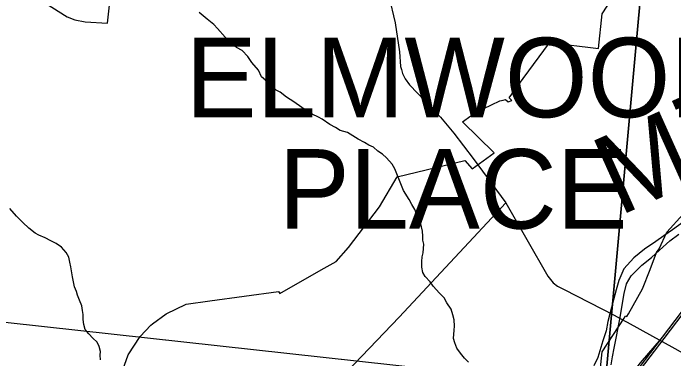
# Model space of a CAD drawing. Extents: x -8.2 to 38.5, y -0.1 to 21.9.
# Drawn here: x 7.39 to 8.176, y 19.91 to 20.321 of the extents above; entities that cross this region are included whole.
import ezdxf

# ---------------------------------------------------------------- set-up
doc = ezdxf.new("R2010")
doc.units = 0
for name, color, linetype in [('Default', 7, 'Continuous'), ('GM_X_Adjacent_County_Text', 7, 'Continuous'), ('GM_X_County_Subdivision', 7, 'Continuous'), ('GM_X_Minor_River', 7, 'Continuous'), ('GM_X_Minor_River_Text', 7, 'Continuous'), ('GM_X_Section_Text', 7, 'Continuous'), ('GM_X_Township_Subdivision_Text', 7, 'Continuous'), ('GM_X_Township_Text', 7, 'Continuous'), ('GM_X_US_Location', 7, 'Continuous')]:
    doc.layers.add(name, color=color, linetype=linetype)

msp = doc.modelspace()

# ---------------------------------------------------------------- linework, layer by layer
at = {"layer": 'Default'}
for points in [[(8.17519, 20.76446), (7.11825, 20.76446), (7.04846, 19.98989), (8.0944, 19.87488)], [(8.88057, 20.76446), (8.17519, 20.76446), (8.0944, 19.87488), (8.96338, 19.73883), (8.96338, 20.75264)]]:
    msp.add_lwpolyline(points, close=True, dxfattribs=at)
msp.add_lwpolyline([(7.51441, 19.87866), (7.52709, 19.91445), (7.54115, 19.93648), (7.5539, 19.94998), (7.55592, 19.95143), (7.57236, 19.96322), (7.59613, 19.97498), (7.62437, 19.9788), (7.70592, 19.98984), (7.70763, 19.98758), (7.7568, 20.01569), (7.77454, 20.02584), (7.7893, 20.04237), (7.82612, 20.09071), (7.84722, 20.1264), (7.92772, 20.14616), (7.93636, 20.13612), (7.96243, 20.15501), (7.9247, 20.19221), (7.93469, 20.19908), (7.93812, 20.20143), (7.94044, 20.20303), (7.95951, 20.21224), (7.96921, 20.21693), (7.97335, 20.21776), (7.97625, 20.21879), (7.97926, 20.21587), (7.98367, 20.21766), (7.98041, 20.22087), (7.99719, 20.24379), (8.02836, 20.28636), (8.04125, 20.28481), (8.07418, 20.28085), (8.08664, 20.27935), (8.09098, 20.32091), (8.11731, 20.36125)], dxfattribs=at)
at = {"layer": 'GM_X_Adjacent_County_Text'}
msp.add_lwpolyline([(7.04846, 19.98989), (8.0944, 19.87488), (7.97887, 18.87016), (6.95853, 18.98963)], close=True, dxfattribs=at)
at = {"layer": 'GM_X_Minor_River'}
for points in [[(7.85471, 20.11044), (7.84432, 20.13593), (7.84105, 20.14173), (7.83441, 20.14915), (7.82958, 20.15347), (7.82397, 20.15705), (7.81877, 20.16177), (7.81351, 20.1642), (7.80827, 20.16739), (7.80078, 20.1714), (7.78806, 20.17937), (7.77938, 20.1819), (7.77377, 20.18548), (7.76702, 20.18909), (7.75807, 20.19543), (7.75356, 20.19746), (7.74605, 20.2011), (7.73894, 20.20548), (7.73372, 20.20905), (7.72401, 20.2158), (7.71541, 20.22136), (7.70796, 20.22728), (7.70309, 20.2297), (7.69864, 20.23401), (7.69415, 20.2368), (7.69048, 20.24185), (7.68564, 20.24579), (7.68205, 20.2535), (7.67431, 20.26285), (7.66956, 20.26984), (7.66252, 20.27689), (7.65577, 20.2805), (7.64798, 20.28757), (7.64242, 20.29305), (7.63318, 20.3032), (7.62913, 20.30789), (7.62094, 20.31458), (7.61164, 20.32246)], [(7.93213, 19.90598), (7.92737, 19.91074), (7.92266, 19.91663), (7.91833, 19.92251), (7.91591, 19.92869), (7.91423, 19.93408), (7.91499, 19.94393), (7.91518, 19.94886), (7.91509, 19.95608), (7.91343, 19.96223), (7.9114, 19.96877), (7.90639, 19.97658), (7.9032, 19.98241), (7.89733, 19.98797), (7.89006, 19.99625), (7.88646, 20.00134), (7.88063, 20.00766), (7.87778, 20.01272), (7.8765, 20.01885), (7.87639, 20.02569), (7.87699, 20.03137), (7.87793, 20.03589), (7.87852, 20.04118), (7.87873, 20.04649), (7.87776, 20.05109), (7.87758, 20.05604), (7.87742, 20.06174), (7.87611, 20.06712), (7.8741, 20.07404), (7.87026, 20.08256), (7.86817, 20.08758), (7.8646, 20.09343), (7.86142, 20.09964), (7.85471, 20.11044)], [(7.49407, 19.90861), (7.49383, 19.91394), (7.49395, 19.91851), (7.49259, 19.92464), (7.49007, 19.92965), (7.48487, 19.93437), (7.48006, 19.93945), (7.47564, 19.9449), (7.47428, 19.95065), (7.4733, 19.95676), (7.47345, 19.96247), (7.47283, 19.96743), (7.47183, 19.97279), (7.46897, 19.97972), (7.46684, 19.98549), (7.46545, 19.9901), (7.46331, 19.99548), (7.46195, 20.00161), (7.46059, 20.00736), (7.45964, 20.01462), (7.45862, 20.01921), (7.45764, 20.02495), (7.45627, 20.0307), (7.45338, 20.03648), (7.44784, 20.04273), (7.44112, 20.0471), (7.43512, 20.05032), (7.42837, 20.05393), (7.42085, 20.05719), (7.41635, 20.05959), (7.40891, 20.06551), (7.40148, 20.07219), (7.39407, 20.07963), (7.38634, 20.08898)], [(8.18928, 20.07372), (8.17467, 20.06336), (8.16468, 20.05633), (8.15507, 20.04967), (8.14162, 20.04043), (8.1289, 20.03003), (8.1169, 20.01696), (8.11095, 20.00301), (8.10771, 19.99206), (8.10445, 19.97996), (8.09791, 19.95425), (8.09581, 19.94326), (8.09179, 19.93118), (8.08611, 19.91153), (8.08099, 19.90137)], [(8.10188, 19.90249), (8.10358, 19.91234), (8.10529, 19.92257), (8.1082, 19.93619), (8.11113, 19.95095), (8.11284, 19.96156), (8.11454, 19.97141), (8.11712, 19.9877), (8.11998, 19.99904), (8.12548, 20.00882), (8.13823, 20.02149), (8.14978, 20.03039), (8.15943, 20.03933), (8.17178, 20.05049), (8.18216, 20.05827)]]:
    msp.add_lwpolyline(points, dxfattribs=at)
at = {"layer": 'GM_X_Section_Text'}
msp.add_lwpolyline([(8.08664, 19.87646), (8.09098, 19.91803), (8.11731, 19.95836), (8.11888, 19.96106), (8.12036, 19.96028), (8.12234, 19.96355), (8.13909, 19.99301), (8.14826, 20.01636), (8.1558, 20.03644), (8.15637, 20.03765), (8.15878, 20.04093), (8.16789, 20.06054), (8.18748, 20.08198)], dxfattribs=at)
at = {"layer": 'GM_X_Township_Subdivision_Text'}
msp.add_lwpolyline([(7.40013, 20.40265), (7.41269, 20.34774), (7.41562, 20.34386), (7.42118, 20.33876), (7.45438, 20.31727), (7.46339, 20.31359), (7.47586, 20.31132), (7.50243, 20.30978), (7.50867, 20.36734), (7.50677, 20.3803), (7.50261, 20.3941), (7.49491, 20.41376)], dxfattribs=at)
at = {"layer": 'GM_X_Township_Text'}
for points in [[(7.83721, 20.34235), (7.84469, 20.30988), (7.84984, 20.27559), (7.85126, 20.2581), (7.85225, 20.25448), (7.85364, 20.24951), (7.85684, 20.24314), (7.86168, 20.23618), (7.89859, 20.19767), (7.91453, 20.17869), (7.93746, 20.14854), (7.97641, 20.09542), (8.02647, 20.00823), (8.03277, 20.00049), (8.03782, 19.9963), (8.04589, 19.99221), (8.10522, 19.96182), (8.11254, 19.95779)], [(7.38927, 19.53661), (7.39594, 19.54811), (7.40527, 19.55894), (7.41743, 19.5691), (7.4376, 19.5841), (7.5541, 19.6716), (7.60693, 19.71127), (7.62543, 19.72677), (7.65394, 19.75491), (7.84937, 19.95949), (7.97641, 20.09542)], [(8.11254, 19.95779), (8.12078, 19.95325), (8.17748, 19.92201), (8.18665, 19.91695)]]:
    msp.add_lwpolyline(points, dxfattribs=at)
at = {"layer": 'GM_X_US_Location'}
for points in [[(7.36387, 19.04639), (7.41591, 19.10159), (7.49331, 19.1836), (7.59753, 19.29364), (7.65625, 19.35588), (7.6834, 19.38472), (7.72777, 19.43149), (7.7971, 19.5053), (7.84789, 19.55902), (7.89217, 19.60594), (7.91784, 19.63299), (7.93925, 19.65618), (7.95733, 19.67597), (7.99335, 19.71755), (8.02419, 19.75465), (8.06578, 19.80791), (8.16286, 19.93568), (8.25321, 20.05471), (8.29997, 20.11571), (8.65685, 20.58718)], [(7.36567, 19.04468), (7.41772, 19.09988), (7.49512, 19.18189), (7.59934, 19.29193), (7.65806, 19.35417), (7.68521, 19.38302), (7.72958, 19.42978), (7.79891, 19.5036), (7.84969, 19.55732), (7.89398, 19.60423), (7.91965, 19.63129), (7.94108, 19.6545), (7.95919, 19.67432), (7.99525, 19.71594), (8.02613, 19.75309), (8.06775, 19.80639), (8.16484, 19.93417), (8.25519, 20.0532), (8.30194, 20.11421), (8.65884, 20.58568)], [(8.12028, 19.88405), (8.13681, 19.90519), (8.16166, 19.9341)]]:
    msp.add_lwpolyline(points, dxfattribs=at)

# ---------------------------------------------------------------- texts
at = {"layer": 'GM_X_County_Subdivision'}
for s, p in [('ELMWOOD', (7.59538, 20.19753)), ('PLACE', (7.70622, 20.06485))]:
    msp.add_text(s, height=0.094697, rotation=0.00001, dxfattribs=at).set_placement(p)
at = {"layer": 'GM_X_Minor_River_Text'}
msp.add_text('Mill', height=0.09468, rotation=24.19198, dxfattribs=at).set_placement((8.11105, 20.07928))

doc.saveas('drawing.dxf')
